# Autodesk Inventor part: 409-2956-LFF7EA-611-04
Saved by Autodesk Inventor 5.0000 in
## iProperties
Created: 2010-06
Part Number: 409-2956-LFF7EA-611-04
Cost Center: 0 lbmass
Material: A36 STEEL PLATE
Document SubType Name: Sheet Metal
Designer: S. Boerckel
Authority: 0 in^3
Mass: 1581.58 g
Surface Area: 388.996 cm^2
Volume: 201.219 cm^3
Density: 7.86 g/cm^3
Flat Pattern Width: 12.7 cm
Flat Pattern Length: 12.7 cm
Flat Pattern Area: 161.29 cm^2
Sheet Metal Rule: 1/2"Thk
Sheet Metal Width: 16.0000 in
Sheet Metal Length: 80.0000 in^2
Description: PUMP FOOT PLATE
User Status: BURN
SaveDate: 2008-01-15
SaveTime: 10:24
FileName: Sheet Metal
Wide: =<Flat Pattern Width>cm
Length: =<Flat Pattern Length>cm
Thickness: 0.5000 in
SMR: =<Sheet Metal Rule> - <Material>
Author: S. Boerckel
Revision Number: 0
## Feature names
1. Hole1
2. Plate1
